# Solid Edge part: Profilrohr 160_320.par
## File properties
Username: ahadarics
Dokumentum tartalom típus: 0
Author: ahadarics
Last saved by: ahadarics
Revision: 88
Sűrűség: 0,000 kg/m^3
Pontosság: 0,990
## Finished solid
Body 1: solid body, 6 faces, 9 edges, 5 vertices.
  Faces by surface: cone 2, cylinder 2, plane 2
  Edges by curve: circle 6, line 3
Bounding box of the edges (mm): 167.000 x 167.000 x 400.000, from (-83.5, -83.5, -347.5) to (83.5, 83.5, 52.5).
Cylindrical faces by radius (mm): R80 x1, R83.5 x1
Conical faces (half-angle, radius in mm at the cone's reference point): 45 deg R80.25 x2
Planar faces by outward normal: +z 1, -z 1
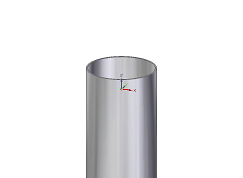
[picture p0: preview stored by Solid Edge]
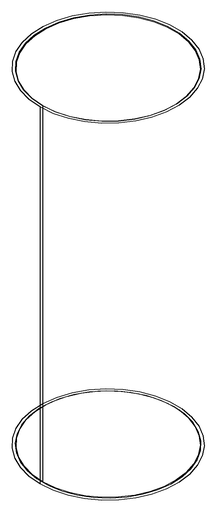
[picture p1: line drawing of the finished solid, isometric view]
